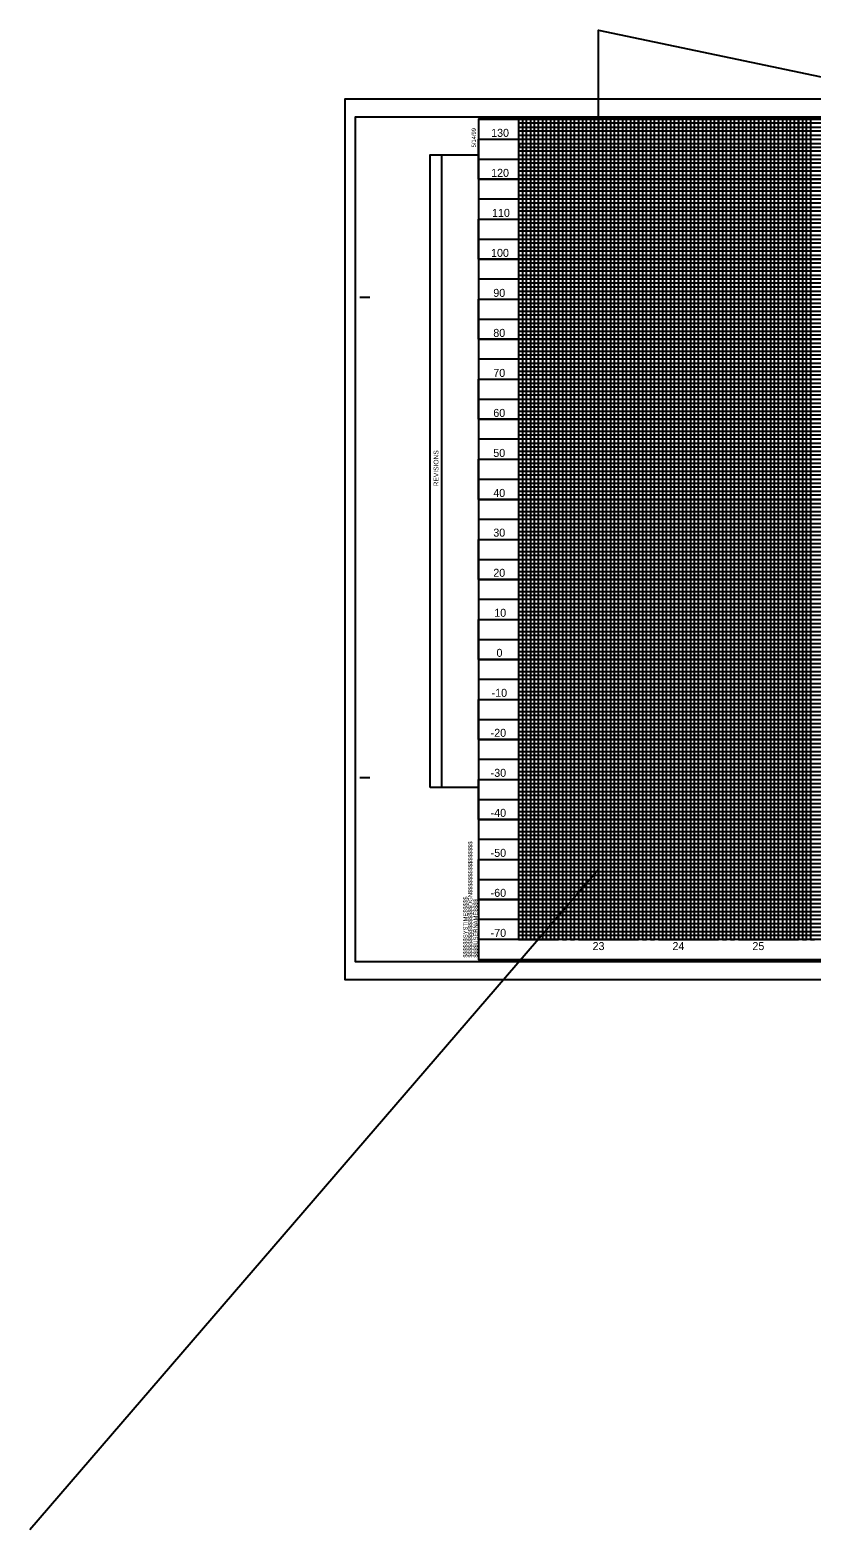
# Model space of a CAD drawing. Extents: x 1633303 to 1635397, y 883210 to 885302.
# Drawn here: x 1633303 to 1634280, y 883210 to 885084 of the extents above; entities that cross this region are included whole.
import ezdxf

# ---------------------------------------------------------------- set-up
doc = ezdxf.new("R2010")
doc.units = 0
for name, color, linetype in [('Exist Vertical Profile Horizontal Axis Label Major', 7, 'Continuous'), ('Exist Vertical Profile Vertical Axis Label', 7, 'Continuous'), ('Scratch_Level_4', 7, 'Continuous'), ('Scratch_Level_8', 7, 'Continuous'), ('Sheet Block Revision CELL', 7, 'Continuous'), ('Sheet Cutting Line CELL', 7, 'Continuous'), ('Sheet DOT Grid CELL', 7, 'Continuous'), ('Sheet Plot Border Inside CELL', 7, 'Continuous'), ('Sheet Plot Border Outside CELL', 7, 'Continuous'), ('Sheet Profile CELL', 7, 'Continuous'), ('Sheet Profile Grid Major CELL', 7, 'Continuous'), ('Sheet Profile Grid Middle CELL', 7, 'Continuous'), ('Sheet Profile Grid Minor CELL', 7, 'Continuous'), ('Stewart Plot Border Xerox6279 and LJ5000', 7, 'Continuous')]:
    doc.layers.add(name, color=color, linetype=linetype)

msp = doc.modelspace()

# ---------------------------------------------------------------- linework, layer by layer
at = {"layer": 'Scratch_Level_4'}
for q in [(1634013.9, 884612.2), (1633303.2, 883209.6)]:
    msp.add_line((1634013.9, 884035.1), q, dxfattribs=at)
at = {"layer": 'Scratch_Level_8'}
msp.add_lwpolyline([(1634013.9, 883947.6), (1634013.9, 885084.1), (1635313.9, 884811.6), (1635263.9, 884541.5), (1635263.9, 883947.6)], close=True, dxfattribs=at)
at = {"layer": 'Sheet Block Revision CELL'}
msp.add_line((1633817.9, 884137.6), (1633817.9, 884928.3), dxfattribs=at)
msp.add_lwpolyline([(1633803.3, 884137.6), (1633803.3, 884928.3), (1633863.9, 884928.3), (1633863.9, 884137.6)], close=True, dxfattribs=at)
at = {"layer": 'Sheet Cutting Line CELL'}
for p, q in [((1635380.9, 884997.6), (1633696.9, 884997.6)), ((1633696.9, 884997.6), (1633696.9, 883897.6)), ((1633696.9, 883897.6), (1635380.9, 883897.6))]:
    msp.add_line(p, q, dxfattribs=at)
at = {"layer": 'Sheet DOT Grid CELL'}
for p, q in [((1633913.9, 884972.6), (1633913.9, 883947.6)), ((1633963.9, 884972.6), (1633963.9, 883947.6)), ((1634013.9, 884972.6), (1634013.9, 883947.6)), ((1634063.9, 884972.6), (1634063.9, 883947.6)), ((1634113.9, 884972.6), (1634113.9, 883947.6)), ((1634163.9, 884972.6), (1634163.9, 883947.6)), ((1634213.9, 884972.6), (1634213.9, 883947.6)), ((1634263.9, 884972.6), (1634263.9, 883947.6)), ((1633863.9, 884947.6), (1635163.8, 884947.6)), ((1633863.9, 884897.6), (1635163.8, 884897.6)), ((1633863.9, 884847.6), (1635163.8, 884847.6)), ((1633863.9, 884797.6), (1635163.8, 884797.6)), ((1633863.9, 884747.6), (1635363.9, 884747.6)), ((1633863.9, 884697.6), (1635363.9, 884697.6)), ((1633863.9, 884647.6), (1635363.9, 884647.6)), ((1633863.9, 884597.6), (1635363.9, 884597.6)), ((1633863.9, 884547.6), (1635363.9, 884547.6)), ((1633863.9, 884497.6), (1635363.9, 884497.6)), ((1633863.9, 884447.6), (1635363.9, 884447.6)), ((1633863.9, 884397.6), (1635363.9, 884397.6)), ((1633863.9, 884347.6), (1635363.9, 884347.6)), ((1633863.9, 884297.6), (1635363.9, 884297.6)), ((1633863.9, 884247.6), (1635363.9, 884247.6)), ((1633863.9, 884197.6), (1635363.9, 884197.6)), ((1633863.9, 884147.6), (1635363.9, 884147.6)), ((1633863.9, 884097.6), (1635363.9, 884097.6)), ((1633863.9, 884047.6), (1635363.9, 884047.6)), ((1633863.9, 883997.6), (1635363.9, 883997.6))]:
    msp.add_line(p, q, dxfattribs=at)
at = {"layer": 'Sheet Plot Border Inside CELL'}
msp.add_lwpolyline([(1635376.4, 884975.2), (1633709.9, 884975.2), (1633709.9, 883920.1), (1635376.4, 883920.1)], close=True, dxfattribs=at)
at = {"layer": 'Sheet Plot Border Outside CELL'}
msp.add_lwpolyline([(1635380.9, 884997.6), (1633696.9, 884997.6), (1633696.9, 883897.6), (1635380.9, 883897.6)], close=True, dxfattribs=at)
at = {"layer": 'Sheet Profile CELL'}
for p, q in [((1633715.4, 884750.1), (1633727.9, 884750.1)), ((1633715.4, 884150.1), (1633727.9, 884150.1)), ((1635363.9, 883947.6), (1633863.9, 883947.6)), ((1633863.9, 883922.6), (1633863.9, 883922.6)), ((1633863.9, 883922.6), (1633863.9, 883922.6)), ((1633863.9, 883922.6), (1633863.9, 883922.6)), ((1633863.9, 883922.6), (1633863.9, 883922.6)), ((1633863.9, 883922.6), (1633863.9, 883922.6)), ((1633863.9, 883922.6), (1633863.9, 883922.6))]:
    msp.add_line(p, q, dxfattribs=at)
msp.add_lwpolyline([(1635363.9, 884972.6), (1633863.9, 884972.6), (1633863.9, 883922.6), (1635363.9, 883922.6)], close=True, dxfattribs=at)
msp.add_lwpolyline([(1633901.4, 883922.6), (1633901.4, 883922.6)], dxfattribs=at)
at = {"layer": 'Sheet Profile Grid Major CELL'}
for points in [[(1633863.9, 884972.6), (1633913.9, 884972.6), (1633913.9, 883947.6), (1633963.9, 883947.6), (1633963.9, 884972.6), (1634013.9, 884972.6), (1634013.9, 883947.6), (1634063.9, 883947.6), (1634063.9, 884972.6), (1634113.9, 884972.6), (1634113.9, 883947.6), (1634163.9, 883947.6), (1634163.9, 884972.6), (1634213.9, 884972.6), (1634213.9, 883947.6), (1634263.9, 883947.6), (1634263.9, 884972.6), (1634313.9, 884972.6)], [(1635163.8, 884897.6), (1633864, 884897.6), (1633864, 884947.6), (1635163.8, 884947.6)], [(1635163.8, 884797.6), (1633863.9, 884797.6), (1633863.9, 884847.6), (1635163.8, 884847.6)], [(1635363.9, 884697.6), (1633863.9, 884697.6), (1633863.9, 884747.6), (1635363.9, 884747.6)], [(1635363.9, 884597.6), (1633863.9, 884597.6), (1633863.9, 884647.6), (1635363.9, 884647.6)], [(1635363.9, 884497.6), (1633863.9, 884497.6), (1633863.9, 884547.6), (1635363.9, 884547.6)], [(1635363.9, 884397.6), (1633863.9, 884397.6), (1633863.9, 884447.6), (1635363.9, 884447.6)], [(1635363.9, 884297.6), (1633863.9, 884297.6), (1633863.9, 884347.6), (1635363.9, 884347.6)], [(1635363.9, 884197.6), (1633863.9, 884197.6), (1633863.9, 884247.6), (1635363.9, 884247.6)], [(1635363.9, 884097.6), (1633863.9, 884097.6), (1633863.9, 884147.6), (1635363.9, 884147.6)], [(1635363.9, 883997.6), (1633863.9, 883997.6), (1633863.9, 884047.6), (1635363.9, 884047.6)]]:
    msp.add_lwpolyline(points, dxfattribs=at)
at = {"layer": 'Sheet Profile Grid Middle CELL'}
for points in [[(1633938.9, 883947.6), (1633938.9, 884972.6), (1633988.9, 884972.6), (1633988.9, 883947.6), (1634038.9, 883947.6), (1634038.9, 884972.6), (1634088.9, 884972.6), (1634088.9, 883947.6), (1634138.9, 883947.6), (1634138.9, 884972.6), (1634188.9, 884972.6), (1634188.9, 883947.6), (1634238.9, 883947.6), (1634238.9, 884972.6), (1634288.9, 884972.6)], [(1633863.9, 884922.6), (1635163.8, 884922.6)], [(1635163.8, 884872.6), (1633863.9, 884872.6), (1633863.9, 884822.6), (1635163.8, 884822.6)], [(1635163.8, 884772.6), (1633863.9, 884772.6), (1633863.9, 884722.6), (1635363.9, 884722.6)], [(1635363.9, 884672.6), (1633863.9, 884672.6), (1633863.9, 884622.6), (1635363.9, 884622.6)], [(1635363.9, 884572.6), (1633863.9, 884572.6), (1633863.9, 884522.6), (1635363.9, 884522.6)], [(1635363.9, 884472.6), (1633863.9, 884472.6), (1633863.9, 884422.6), (1635363.9, 884422.6)], [(1635363.9, 884372.6), (1633863.9, 884372.6), (1633863.9, 884322.6), (1635363.9, 884322.6)], [(1635363.9, 884272.6), (1633863.9, 884272.6), (1633863.9, 884222.6), (1635363.9, 884222.6)], [(1635363.9, 884172.6), (1633863.9, 884172.6), (1633863.9, 884122.6), (1635363.9, 884122.6)], [(1635363.9, 884072.6), (1633863.9, 884072.6), (1633863.9, 884022.6), (1635363.9, 884022.6)], [(1635363.9, 883972.6), (1633863.9, 883972.6)]]:
    msp.add_lwpolyline(points, dxfattribs=at)
at = {"layer": 'Sheet Profile Grid Minor CELL'}
for p, q in [((1635163.8, 884792.6), (1633913.9, 884792.6)), ((1633913.9, 884792.6), (1633913.9, 884787.6)), ((1633913.9, 884787.6), (1635163.8, 884787.6)), ((1635313.9, 884767.6), (1633913.9, 884767.6))]:
    msp.add_line(p, q, dxfattribs=at)
for points in [[(1633918.9, 884972.6), (1633923.9, 884972.6), (1633928.9, 884972.6), (1633933.9, 884972.6), (1633943.9, 884972.6), (1633910.8, 884972.6), (1633915.8, 884972.6), (1633873.9, 884972.6), (1633878.9, 884972.6), (1633883.9, 884972.6), (1633893.9, 884972.6), (1633898.9, 884972.6), (1633903.9, 884972.6), (1633908.9, 884972.6), (1633918.9, 884972.6), (1633918.9, 883947.6), (1633923.9, 883947.6), (1633923.9, 884972.6), (1633928.9, 884972.6), (1633928.9, 883947.6), (1633933.9, 883947.6), (1633933.9, 884972.6), (1633943.9, 884972.6), (1633943.9, 883947.6), (1633948.9, 883947.6), (1633948.9, 884972.6), (1633953.9, 884972.6), (1633953.9, 883947.6), (1633958.9, 883947.6), (1633958.9, 884972.6), (1633968.9, 884972.6), (1633968.9, 883947.6), (1633973.9, 883947.6), (1633973.9, 884972.6), (1633978.9, 884972.6), (1633978.9, 883947.6), (1633983.9, 883947.6), (1633983.9, 884972.6), (1633993.9, 884972.6), (1633993.9, 883947.6), (1633998.9, 883947.6), (1633998.9, 884972.6), (1634003.9, 884972.6), (1634003.9, 883947.6), (1634008.9, 883947.6), (1634008.9, 884972.6), (1634018.9, 884972.6), (1634018.9, 883947.6), (1634023.9, 883947.6), (1634023.9, 884972.6), (1634028.9, 884972.6), (1634028.9, 883947.6), (1634033.9, 883947.6), (1634033.9, 884972.6), (1634043.9, 884972.6), (1634043.9, 883947.6), (1634048.9, 883947.6), (1634048.9, 884972.6), (1634053.9, 884972.6), (1634053.9, 883947.6), (1634058.9, 883947.6), (1634058.9, 884972.6), (1634068.9, 884972.6), (1634068.9, 883947.6), (1634073.9, 883947.6), (1634073.9, 884972.6), (1634078.9, 884972.6), (1634078.9, 883947.6)], [(1635163.8, 884967.6), (1633913.9, 884967.6), (1633913.9, 884962.6), (1635163.8, 884962.6)], [(1635163.8, 884957.6), (1633913.9, 884957.6), (1633913.9, 884952.6), (1635163.8, 884952.6)], [(1634078.9, 883947.6), (1634083.9, 883947.6), (1634083.9, 884972.6), (1634093.9, 884972.6), (1634093.9, 883947.6), (1634098.9, 883947.6), (1634098.9, 884972.6), (1634103.9, 884972.6), (1634103.9, 883947.6), (1634108.9, 883947.6), (1634108.9, 884972.6), (1634118.9, 884972.6), (1634118.9, 883947.6), (1634123.9, 883947.6), (1634123.9, 884972.6), (1634123.9, 884972.6), (1634128.9, 884972.6), (1634128.9, 883947.6), (1634133.9, 883947.6), (1634133.9, 884972.6), (1634143.9, 884972.6), (1634143.9, 883947.6), (1634148.9, 883947.6), (1634148.9, 884972.6), (1634153.9, 884972.6), (1634153.9, 883947.6), (1634158.9, 883947.6), (1634158.9, 884972.6), (1634168.9, 884972.6), (1634168.9, 883947.6), (1634173.9, 883947.6), (1634173.9, 884972.6), (1634178.9, 884972.6), (1634178.9, 883947.6), (1634183.9, 883947.6), (1634183.9, 884972.6), (1634193.9, 884972.6), (1634193.9, 883947.6), (1634198.9, 883947.6), (1634198.9, 884972.6), (1634203.9, 884972.6), (1634203.9, 883947.6), (1634208.9, 883947.6), (1634208.9, 884972.6), (1634218.9, 884972.6), (1634218.9, 883947.6), (1634223.9, 883947.6), (1634223.9, 884972.6), (1634228.9, 884972.6), (1634228.9, 883947.6), (1634233.9, 883947.6), (1634233.9, 884972.6), (1634243.9, 884972.6), (1634243.9, 883947.6), (1634258.9, 883947.6), (1634258.9, 884972.6), (1634268.9, 884972.6), (1634268.9, 883947.6), (1634273.9, 883947.6), (1634273.9, 884972.6), (1634278.9, 884972.6), (1634278.9, 883947.6), (1634283.9, 883947.6)], [(1634248.9, 884972.6), (1634248.9, 883947.6), (1634253.9, 883947.6), (1634253.9, 884972.6)], [(1634248.9, 884972), (1634248.9, 883947.6), (1634253.9, 883947.6), (1634253.9, 884972)], [(1635163.8, 884941.9), (1633914.9, 884941.9), (1633914.9, 884937.6), (1635163.8, 884937.6)], [(1635163.8, 884932.6), (1633913.9, 884932.6), (1633913.9, 884927.6), (1635163.8, 884927.6)], [(1635163.8, 884917.6), (1633913.9, 884917.6), (1633913.9, 884912.6), (1635163.8, 884912.6)], [(1635163.8, 884907.6), (1633913.9, 884907.6), (1633913.9, 884902.6), (1635163.8, 884902.6)], [(1635163.8, 884892.6), (1633913.9, 884892.6), (1633913.9, 884887.6), (1635163.8, 884887.6)], [(1635163.8, 884882.6), (1633913.9, 884882.6), (1633913.9, 884877.6), (1635163.8, 884877.6)], [(1635163.8, 884867.6), (1633913.9, 884867.6), (1633913.9, 884862.6), (1635163.8, 884862.6)], [(1635163.8, 884857.6), (1633913.9, 884857.6), (1633913.9, 884852.6), (1635163.8, 884852.6)], [(1635163.8, 884842.6), (1633913.9, 884842.6), (1633913.9, 884837.6), (1635163.8, 884837.6)], [(1635163.8, 884832.6), (1633913.9, 884832.6), (1633913.9, 884832.6), (1633913.9, 884812.6), (1635163.8, 884812.6)], [(1633913.9, 884827.6), (1635163.8, 884827.6)], [(1635163.8, 884817.6), (1633913.9, 884817.6)], [(1635163.8, 884807.6), (1633913.9, 884807.6), (1633913.9, 884802.6), (1635163.8, 884802.6)], [(1635163.8, 884782.6), (1633913.9, 884782.6), (1633913.9, 884777.6), (1635163.8, 884777.6)], [(1635313.9, 884762.6), (1633913.9, 884762.6), (1633913.9, 884757.6), (1635313.9, 884757.6)], [(1635313.9, 884752.6), (1633913.9, 884752.6)], [(1633913.9, 884742.6), (1635313.9, 884742.6)], [(1635313.9, 884737.6), (1633913.9, 884737.6), (1633913.9, 884732.6), (1635313.9, 884732.6)], [(1635313.9, 884727.6), (1633913.9, 884727.6), (1633913.9, 884717.6), (1635313.9, 884717.6)], [(1635313.9, 884712.6), (1633913.9, 884712.6), (1633913.9, 884707.6), (1635313.9, 884707.6)], [(1635313.9, 884702.6), (1633913.9, 884702.6), (1633913.9, 884692.6), (1635313.9, 884692.6)], [(1635313.9, 884687.6), (1633913.9, 884687.6), (1633913.9, 884682.6), (1635313.9, 884682.6)], [(1635313.9, 884677.6), (1633913.9, 884677.6), (1633913.9, 884667.6), (1635313.9, 884667.6)], [(1635313.9, 884662.6), (1633913.9, 884662.6), (1633913.9, 884657.6), (1635313.9, 884657.6)], [(1635313.9, 884652.6), (1633913.9, 884652.6), (1633913.9, 884642.6), (1635313.9, 884642.6)], [(1635313.9, 884637.6), (1633913.9, 884637.6), (1633913.9, 884632.6), (1635313.9, 884632.6)], [(1635313.9, 884627.6), (1633913.9, 884627.6), (1633913.9, 884617.6), (1635313.9, 884617.6)], [(1635313.9, 884612.6), (1633913.9, 884612.6), (1633913.9, 884607.6), (1635313.9, 884607.6)], [(1635313.9, 884602.6), (1633913.9, 884602.6), (1633913.9, 884592.6), (1635313.9, 884592.6)], [(1635313.9, 884587.6), (1633913.9, 884587.6), (1633913.9, 884582.6), (1635313.9, 884582.6)], [(1635313.9, 884577.6), (1633913.9, 884577.6), (1633913.9, 884567.6), (1635313.9, 884567.6)], [(1635313.9, 884562.6), (1633913.9, 884562.6), (1633913.9, 884557.6), (1635313.9, 884557.6)], [(1635313.9, 884552.6), (1633913.9, 884552.6), (1633913.9, 884542.6), (1635313.9, 884542.6)], [(1635313.9, 884537.6), (1633913.9, 884537.6), (1633913.9, 884532.6), (1635313.9, 884532.6)], [(1635313.9, 884527.6), (1633913.9, 884527.6), (1633913.9, 884517.6), (1635313.9, 884517.6)], [(1635313.9, 884512.6), (1633913.9, 884512.6), (1633913.9, 884507.6), (1635313.9, 884507.6)], [(1635313.9, 884502.6), (1633913.9, 884502.6), (1633913.9, 884492.6), (1635313.9, 884492.6)], [(1635313.9, 884487.6), (1633913.9, 884487.6), (1633913.9, 884482.6), (1635313.9, 884482.6)], [(1635313.9, 884477.6), (1633913.9, 884477.6), (1633913.9, 884467.6), (1635313.9, 884467.6)], [(1635313.9, 884462.6), (1633913.9, 884462.6), (1633913.9, 884457.6), (1635313.9, 884457.6)], [(1635313.9, 884452.6), (1633913.9, 884452.6)], [(1633913.9, 884442.6), (1635313.9, 884442.6)], [(1635313.9, 884437.6), (1633913.9, 884437.6), (1633913.9, 884432.6), (1635313.9, 884432.6)], [(1635313.9, 884427.6), (1633913.9, 884427.6), (1633913.9, 884417.6), (1635313.9, 884417.6)], [(1635313.9, 884412.6), (1633913.9, 884412.6), (1633913.9, 884407.6), (1635313.9, 884407.6)], [(1635313.9, 884402.6), (1633913.9, 884402.6), (1633913.9, 884392.6), (1635313.9, 884392.6)], [(1635313.9, 884387.6), (1633913.9, 884387.6), (1633913.9, 884382.6), (1635313.9, 884382.6)], [(1635313.9, 884377.6), (1633913.9, 884377.6), (1633913.9, 884367.6), (1635313.9, 884367.6)], [(1635313.9, 884362.6), (1633913.9, 884362.6), (1633913.9, 884357.6), (1635313.9, 884357.6)], [(1635313.9, 884352.6), (1633913.9, 884352.6), (1633913.9, 884342.6), (1635313.9, 884342.6)], [(1635313.9, 884337.6), (1633913.9, 884337.6), (1633913.9, 884332.6), (1635313.9, 884332.6)], [(1635313.9, 884327.6), (1633913.9, 884327.6), (1633913.9, 884317.6), (1635313.9, 884317.6)], [(1635313.9, 884312.6), (1633913.9, 884312.6), (1633913.9, 884307.6), (1635313.9, 884307.6)], [(1635313.9, 884302.6), (1633913.9, 884302.6), (1633913.9, 884292.6), (1635313.9, 884292.6)], [(1635313.9, 884287.6), (1633913.9, 884287.6), (1633913.9, 884282.6), (1635313.9, 884282.6)], [(1635313.9, 884277.6), (1633913.9, 884277.6), (1633913.9, 884267.6), (1635313.9, 884267.6)], [(1635313.9, 884262.6), (1633913.9, 884262.6), (1633913.9, 884257.6), (1635313.9, 884257.6)], [(1635313.9, 884252.6), (1633913.9, 884252.6), (1633913.9, 884242.6), (1635313.9, 884242.6)], [(1635313.9, 884237.6), (1633913.9, 884237.6), (1633913.9, 884232.6), (1635313.9, 884232.6)], [(1635313.9, 884227.6), (1633913.9, 884227.6), (1633913.9, 884217.6), (1635313.9, 884217.6)], [(1635313.9, 884212.6), (1633913.9, 884212.6), (1633913.9, 884207.6), (1635313.9, 884207.6)], [(1635313.9, 884202.6), (1633913.9, 884202.6), (1633913.9, 884192.6), (1635313.9, 884192.6)], [(1635313.9, 884187.6), (1633913.9, 884187.6), (1633913.9, 884182.6), (1635313.9, 884182.6)], [(1635313.9, 884177.6), (1633913.9, 884177.6), (1633913.9, 884167.6), (1635313.9, 884167.6)], [(1635313.9, 884162.6), (1633913.9, 884162.6), (1633913.9, 884157.6), (1635313.9, 884157.6)], [(1635313.9, 884152.6), (1633913.9, 884152.6)], [(1633913.9, 884142.6), (1635313.9, 884142.6)], [(1635313.9, 884137.6), (1633913.9, 884137.6), (1633913.9, 884132.6), (1635313.9, 884132.6)], [(1635313.9, 884127.6), (1633913.9, 884127.6)], [(1633913.9, 884117.6), (1635313.9, 884117.6)], [(1635313.9, 884112.6), (1633913.9, 884112.6), (1633913.9, 884107.6), (1635313.9, 884107.6)], [(1635313.9, 884102.6), (1633913.9, 884102.6), (1633913.9, 884092.6), (1635313.9, 884092.6)], [(1635313.9, 884087.6), (1633913.9, 884087.6), (1633913.9, 884082.6), (1635313.9, 884082.6)], [(1635313.9, 884077.6), (1633913.9, 884077.6), (1633913.9, 884067.6), (1635313.9, 884067.6)], [(1635313.9, 884062.6), (1633913.9, 884062.6), (1633913.9, 884057.6), (1635313.9, 884057.6)], [(1635313.9, 884052.6), (1633913.9, 884052.6), (1633913.9, 884042.6), (1635313.9, 884042.6)], [(1635313.9, 884037.6), (1633913.9, 884037.6), (1633913.9, 884032.6), (1635313.9, 884032.6)], [(1635313.9, 884027.6), (1633913.9, 884027.6), (1633913.9, 884017.6), (1635313.9, 884017.6)], [(1635313.9, 884012.6), (1633913.9, 884012.6), (1633913.9, 884007.6), (1635313.9, 884007.6)], [(1635313.9, 884002.6), (1633913.9, 884002.6), (1633913.9, 883992.6), (1635313.9, 883992.6)], [(1635313.9, 883987.6), (1633913.9, 883987.6), (1633913.9, 883982.6), (1635313.9, 883982.6)], [(1635313.9, 883977.6), (1633913.9, 883977.6), (1633913.9, 883967.6), (1635313.9, 883967.6)], [(1635313.9, 883962.6), (1633913.9, 883962.6), (1633913.9, 883957.6), (1635313.9, 883957.6)], [(1635313.9, 883952.6), (1633913.9, 883952.6)]]:
    msp.add_lwpolyline(points, dxfattribs=at)
at = {"layer": 'Stewart Plot Border Xerox6279 and LJ5000'}
msp.add_lwpolyline([(1633696.9, 883897.6), (1635396.9, 883897.6), (1635396.9, 884997.6), (1633696.9, 884997.6)], close=True, dxfattribs=at)

# ---------------------------------------------------------------- texts
at = {"layer": 'Exist Vertical Profile Horizontal Axis Label Major'}
for s, p in [('23', (1634006.5, 883934.3)), ('24', (1634106.4, 883934.3)), ('25', (1634206.3, 883934.3))]:
    msp.add_text(s, height=10, dxfattribs=at).set_placement(p)
at = {"layer": 'Exist Vertical Profile Vertical Axis Label'}
for s, p in [('130', (1633879.7, 884950.6)), ('120', (1633879.7, 884900.6)), ('110', (1633880.8, 884850.6)), ('100', (1633879.6, 884800.6)), ('90', (1633882.4, 884750.6)), ('80', (1633882.4, 884700.6)), ('70', (1633882.4, 884650.6)), ('60', (1633882.4, 884600.6)), ('50', (1633882.4, 884550.6)), ('40', (1633882.4, 884500.6)), ('30', (1633882.4, 884451)), ('20', (1633882.4, 884400.8)), ('10', (1633883.6, 884350.8)), ('0', (1633886.4, 884300.8)), ('-10', (1633880.3, 884250.8)), ('-20', (1633879.1, 884200.8)), ('-30', (1633879.1, 884150.8)), ('-40', (1633879.1, 884100.8)), ('-50', (1633879.1, 884050.8)), ('-60', (1633879.1, 884000.8)), ('-70', (1633879.1, 883950.8))]:
    msp.add_text(s, height=10, dxfattribs=at).set_placement(p)
at = {"layer": 'Sheet Block Revision CELL'}
msp.add_text('REVISIONS', height=6, rotation=90, dxfattribs=at).set_placement((1633813.8, 884513.8))
at = {"layer": 'Sheet Profile CELL'}
for s, p in [('5/14/99', (1633860.6, 884937.4)), ('$$$$$$$$$$$$$$$$DGN$$$$$$$$$$$$$$$$', (1633856.2, 883925)), ('$$$$$$SYSTIME$$$$$', (1633850.2, 883925)), ('$$$$USERNAME$$$$', (1633862.8, 883925))]:
    msp.add_text(s, height=5.25, rotation=90, dxfattribs=at).set_placement(p)

doc.saveas('drawing.dxf')
